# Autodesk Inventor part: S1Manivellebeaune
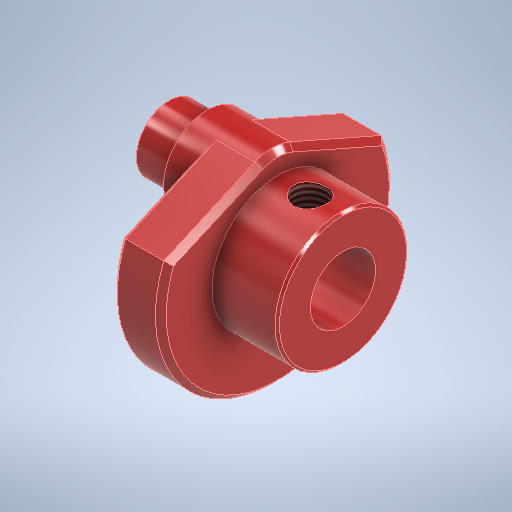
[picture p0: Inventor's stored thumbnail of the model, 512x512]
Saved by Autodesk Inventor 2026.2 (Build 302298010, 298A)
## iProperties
Created: 2026-04
Part Number: S1Manivellebeaune
Material: Générique
Document SubType Name: Modeling
Designer: mel
Density: 1 g/cm^3
Appearance: Rouge
Author: mel
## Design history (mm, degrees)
sketch "Esquisse1"
  geometry: L1 (0, 0)-(0.6, 0); L2 (4.5, 6.05)-(4.5, 10.75); L3 (4.5, 10.75)-(0, 10.75); L4 (0, 10.75)-(0, 0); L5 (10.5, 0)-(10.5, 6.05); L6 (10.5, 6.05)-(4.5, 6.05); L7 (10.5, 3)-(0.6, 3); L8 (0.6, 3)-(0.6, 0); L9 (4.5, 0)-(10.5, 0); L10 (10.5, 0)-(10.5, 3)
  constraints: 20 end point, 4 parallel, 2 horizontal, 2 perpendicular, 1 point on line
  dimensions: "d0" = 4.5 distance of L3.end L2.end; "d1" = 10.75 distance of L9.start L2.end; "d2" = 6 distance of L2.start L5.end; "d3" = 6.05 distance of L5.end L5.start; "d5" = 9.9 distance between parallel lines of L5 L8
revolve "Révolution1" sketch "Esquisse1" stored, may be unused: angle "d6" = 90 deg
sketch "Esquisse2"
  geometry: C1 r 4 at (0, 4); 1 further point
  constraints: 1 centre point
  dimensions: "d7" = 4 distance of C1.centre point (0, 0); "d8" = 8 diameter of C1
extrude "Extrusion1" join sketch "Esquisse2" distance "d9" = 2; taper "d10" = 0 deg
sketch "Esquisse3"
  geometry: C1 r 3 at (0, 0); 2 further points
  constraints: 1 centre point, 1 coincident, 1 vertical alignment
  dimensions: "d11" = 6 diameter of C1
extrude "Extrusion2" join sketch "Esquisse3" distance "d12" = 3.5; taper "d13" = 0 deg
sketch "Esquisse4"
  geometry: C1 r 3 at (0, 0) reference; 1 further point
hole "Perçage1" sketch "Esquisse4" at (0, 0) diameter "d14" = 3.242; stored, may be unused: countersink angle "d18" = 82 deg, drill point angle "d20" = 0 deg; dims "d15" = 4, "d16" = 3.023, "d17" = 2, "d19" = 10
sketch "Esquisse5"
  geometry: L1 (1.61, 7.662)-(11.21, 3.442); L2 (11.21, 3.442)-(6.189, 14.914); L3 (6.189, 14.914)-(-9.403, 15.098); L4 (-9.403, 15.098)-(-15.822, 1.414); L5 (-1.61, 7.662)-(-15.822, 1.414); L6 (0, -15.92)-(0, 20.268) reference; A1 r 4 centre (0, 4) between (0, 0) and (1.61, 7.662) reference
  constraints: 10 end point, 2 point on circle, 2 tangent
  dimensions: "d21" = 132.54 deg angle of L1 L5; "d22" = 113.73 deg angle of L6 L5
extrude "Extrusion3" cut sketch "Esquisse5" extent not by distance; stored distance "d23" = 0; taper "d24" = 0 deg
chamfer "Chanfrein1" distance "d25" = 0.5; stored, may be unused: second distance "d26" = 2, angle "d27" = 45 deg
chamfer "Chanfrein2" distance "d28" = 0.2; stored, may be unused: second distance "d29" = 2, angle "d30" = 45 deg
sketch "Esquisse6"
  geometry: L1 (-10.5, -5.85)-(-10.5, 5.85) reference; C1 r 1.5 at (-7.5, 0); 1 further point
  constraints: 1 centre point
  dimensions: "d31" = 3 diameter of C1; "d32" = 3 distance from line of L1 C1.centre
extrude "Extrusion4" cut sketch "Esquisse6" distance "d33" = 10; taper "d34" = 0 deg
feature "Filetage1" dims "d35" = 4, "d36" = 0
node "Solide1"
